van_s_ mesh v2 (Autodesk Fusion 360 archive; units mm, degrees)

design "van_s_ mesh" references "Solar Panel -  1 - Part 1"
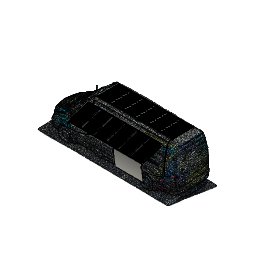
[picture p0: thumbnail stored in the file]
description: Part Number
part number: 6575N187_T-Slotted Framing Rail
base_feature "Base Feature1"
sketch "Sketch2" plane through (0, 0, 0) normal (0, 0, 1) x axis (1, 0, 0)
  line L1 (-2036.5472, 646.9234) -> (2036.5472, 646.9234)
  line L2 (-2036.5472, -646.9234) -> (-2036.5472, 646.9234)
  line L3 (2036.5472, -646.9234) -> (-2036.5472, -646.9234)
  line L4 (2036.5472, 646.9234) -> (2036.5472, -646.9234)
  line L5 (-2036.5472, -646.9234) -> (2036.5472, 646.9234)
  line L6 (2036.5472, -646.9234) -> (-2036.5472, 646.9234)
  line L7 (780, 700) -> (-780, 700)
  line L8 (780, 0) -> (780, 700)
  line L9 (-780, 0) -> (780, 0)
  line L10 (-780, 700) -> (-780, 0)
  point P6 (0, 0)
  point P1 (0, 0)
  point P7 (-780, 700)
  point P10 (-780, 0)
  point P8 (780, 700)
  horizontal L1
  perpendicular L1 L2
  parallel L1 L3
  parallel L2 L4
  coincident L5 P6
  coincident L6 P6
  coincident P1 P6
  horizontal L7
  vertical L8
  horizontal L9
  vertical L10
  midpoint P6 L9
  dimension "d1" distance P7 P10 = 700
  dimension "d2" distance P7 P8 = 1560
extrude "Extrude1" new body sketch "Sketch2" profile of L7 L8 L9 L10 along normal blind 4
copy_paste_bodies "CopyPasteBodies1"
move "Move1"
copy_paste_bodies "CopyPasteBodies2"
move "Move2"
move "Move3"
move "Move4"
move "Move5"
move "Move6"
move "Move7"
copy_paste_bodies "CopyPasteBodies3"
move "Move8"
copy_paste_bodies "CopyPasteBodies4"
move "Move9"
scale "Scale1" ScaleY 0.75
move "Move10"
sketch "Sketch3" plane through (0, 0, 0) normal (0, 0, 1) x axis (1, 0, 0)
work_plane "WorkPlane1" AlongDistance -2099.524
sketch "Sketch4" plane through (-2099.524, 0, 0) normal (1, 0, 0) x axis (0, 1, 0)
  curve K1 (-814.2732, -244.8153) -> (-965.3731, -1472.4732)
sketch "Sketch5" plane through (-2099.524, 0, 0) normal (1, 0, 0) x axis (0, 1, 0)
  line L1 (-843.7082, -238.4309) -> (-814.6312, -245.8155)
  line L2 (-997.4951, -1471.5228) -> (-967.4951, -1471.5061)
  arc A1 centre (4000.6368, -1468.7367) radius 4968.1327 clockwise from (-967.4951, -1471.5061) to (-814.6312, -245.8155)
  arc A2 centre (4000.6368, -1468.7367) radius 4998.1327 clockwise from (-997.4951, -1471.5228) to (-843.7082, -238.4309)
  dimension "d12" = 30
extrude "Extrude2" new body sketch "Sketch5" distance 40
work_plane "WorkPlane2" AlongDistance -996.132
sketch "Sketch6" plane through (0, -996.132, 0) normal (0, 1, 0) x axis (1, 0, 0)
  line L1 (-577.0426, 2211.136) -> (-2073.8842, 2211.136)
  line L2 (-577.0426, 61.2365) -> (-577.0426, 2211.136)
  line L3 (-2073.8842, 61.2365) -> (-577.0426, 61.2365)
  line L4 (-2073.8842, 2211.136) -> (-2073.8842, 61.2365)
  horizontal L1
  vertical L2
  horizontal L3
  vertical L4
work_plane "WorkPlane3" AlongDistance -2035.729
sketch "Sketch7" plane through (-2035.729, 0, 0) normal (1, 0, 0) x axis (0, 1, 0)
  arc A1 centre (3368.2029, -1386.2856) radius 4337.2066 clockwise from (-882.0776, -2250.2745) to (-772.1405, -94.4197)
extrude "Extrude3" new body blind 1452.679 second side blind 46.499
thicken "Thicken1" Thickness 12.67 bodies "mock door"
copy_paste_bodies "CopyPasteBodies5"
move "Move11"
copy_paste_bodies "CopyPasteBodies6"
move "Move12"
copy_paste_bodies "CopyPasteBodies7"
move "Move13"
sketch "Sketch8" plane through (0, 0, 0) normal (0, 0, 1) x axis (1, 0, 0)
remove_instance "RemoveInstance1"
sketch "Sketch9" plane through (0, 0, 0) normal (0, 0, 1) x axis (1, 0, 0)
  line L1 (1822.8151, -997.4951) -> (1782.8151, -997.4951)
  line L2 (1822.8151, -843.7082) -> (1822.8151, -997.4959)
  line L3 (1782.8151, -843.7082) -> (1822.8151, -843.7082)
  line L4 (1782.8151, -997.4959) -> (1782.8151, -843.7082)
  line L5 (-2079.524, -997.4951) -> (-2119.524, -997.4951)
  line L6 (-2079.524, -843.7082) -> (-2079.524, -997.4959)
  line L7 (-2119.524, -843.7082) -> (-2079.524, -843.7082)
  line L8 (-2119.524, -997.4959) -> (-2119.524, -843.7082)
  line L9 (-2079.524, -843.7082) -> (-2119.524, -843.7082)
  line L10 (-2079.524, 649.0832) -> (-2079.524, -843.7082)
  line L11 (-2119.524, 649.0832) -> (-2079.524, 649.0832)
  line L12 (-2119.524, -843.7082) -> (-2119.524, 649.0832)
  line L13 (1822.8151, -843.7082) -> (1782.8151, -843.7082)
  line L14 (1822.8151, 617.5114) -> (1822.8151, -843.7082)
  line L15 (1782.8151, 617.5114) -> (1822.8151, 617.5114)
  line L16 (1782.8151, -843.7082) -> (1782.8151, 617.5114)
  line L17 (-2155.2321, 574.112) -> (1869.3896, 574.112)
  line L18 (-2155.2321, 534.112) -> (-2155.2321, 574.112)
  line L19 (1869.3896, 534.112) -> (-2155.2321, 534.112)
  line L20 (1869.3896, 574.112) -> (1869.3896, 534.112)
  line L21 (2.5, 0) -> (20, 0)
  line L22 (1869.3896, -534.112) -> (-2155.2321, -534.112)
  line L23 (1869.3896, -574.112) -> (1869.3896, -534.112)
  line L24 (-2155.2321, -534.112) -> (-2155.2321, -574.112)
  line L25 (-2155.2321, -574.112) -> (1869.3896, -574.112)
  point P12 (-2119.524, -843.7082)
  point P14 (-2119.524, -843.7082)
  point P11 (-2079.524, -843.7082)
  point P6 (1782.8151, -843.7082)
  point P18 (1782.8151, -843.7082)
  point P5 (1822.8151, -843.7082)
  point P22 (1869.3896, 574.112)
  point P30 (1869.3896, -574.112)
  point P23 (-2155.2321, 574.112)
  point P31 (-2155.2321, -574.112)
  point P24 (-2155.2321, 534.112)
  point P28 (-2155.2321, -534.112)
  point P25 (1869.3896, 534.112)
  point P29 (1869.3896, -534.112)
  horizontal L9
  vertical L10
  horizontal L11
  vertical L12
  coincident P12 P14
  coincident P11 L10
  horizontal L13
  vertical L14
  horizontal L15
  vertical L16
  coincident P6 P18
  coincident P5 L14
  horizontal L17
  vertical L18
  horizontal L19
  vertical L20
  symmetric P22 L21 P30
  symmetric P23 L21 P31
  symmetric P24 L21 P28
  symmetric P25 L21 P29
  dimension "d22" distance P23 P24 = 40
extrude "Extrude4" new body sketch "Sketch9" profile of L17 L18 L19 L20 L22 L23 L24 L25 along normal blind 25
sketch "Sketch10" plane through (0, 0, 25) normal (0, 0, 1) x axis (-1, 0, 0)
  line L1 (-1869.3896, -574.112) -> (-1869.3896, -534.112)
  line L2 (2155.2321, -574.112) -> (-1869.3896, -574.112)
  line L3 (2155.2321, -534.112) -> (2155.2321, -574.112)
  line L4 (-1869.3896, -534.112) -> (2155.2321, -534.112)
  line L5 (2119.524, 843.7082) -> (2119.524, -649.0832)
  line L6 (-1822.8151, -617.5114) -> (-1822.8151, 843.7082)
  line L7 (-1822.8151, -574.112) -> (2119.524, -574.112)
  line L8 (-1822.8151, 575.888) -> (-1822.8151, -574.112)
  line L9 (2119.524, 575.888) -> (-1822.8151, 575.888)
  line L10 (2119.524, -574.112) -> (2119.524, 575.888)
  line L11 (2119.524, 0.888) -> (0, 0)
  line L12 (2079.524, -534.112) -> (2079.524, 535.888)
  line L13 (-1782.8151, -534.112) -> (2079.524, -534.112)
  line L14 (-1782.8151, 535.888) -> (-1782.8151, -534.112)
  line L15 (2079.524, 535.888) -> (-1782.8151, 535.888)
  point P12 (-1822.8151, 575.888)
  point P10 (2119.524, -574.112)
  point P1 (0, 0)
  point P14 (0, 0)
  point P15 (2119.524, 0.888)
  point P11 (-1822.8151, -574.112)
  horizontal L7
  vertical L8
  horizontal L9
  vertical L10
  coincident L6 P12
  coincident L5 P10
  coincident L2 P10
  coincident P1 P14
  midpoint L10 P15
  dimension "d25" distance P11 P12 = 1150
  dimension "d26" = 40
extrude "Extrude5" new body sketch "Sketch10" profile of L2 L4 L5 L6 L7 L8 L9 L10 L15 L14 L13 L12 along normal blind 40
work_plane "WorkPlane4"
sketch "Sketch11" plane through (0, 574.112, 0) normal (0, 1, 0) x axis (-1, 0, 0)
  line L1 (2119.524, 25) -> (-1822.8151, 25)
  line L2 (2119.524, 65) -> (2119.524, 25)
  line L3 (-1822.8151, 65) -> (2119.524, 65)
  line L4 (-1822.8151, 25) -> (-1822.8151, 65)
copy_paste_bodies "CopyPasteBodies8"
move "Move14"
sketch "Sketch12" plane through (-2119.524, 0, 0) normal (-1, 0, 0) x axis (0, -1, 0)
  line L1 (575.888, 75) -> (-574.112, 75)
  line L2 (575.888, 115) -> (575.888, 75)
  line L3 (-574.112, 115) -> (575.888, 115)
  line L4 (-574.112, 75) -> (-574.112, 115)
  line L5 (814.6312, -245.8155) -> (843.7082, -238.4309)
  line L6 (997.4951, -1471.5228) -> (967.4951, -1471.5061)
  line L7 (575.888, 65) -> (575.888, 25)
  curve K1 (843.7082, -238.4309) -> (575.888, 65)
  curve K2 (853.8697, -278.4421) -> (833.5466, -198.4197)
  curve K3 (636.8867, 65) -> (514.8894, 65)
  curve K4 (814.6312, -245.8155) -> (575.888, 25)
  curve K5 (621.2142, 25) -> (530.5619, 25)
  curve K6 (827.5497, -296.682) -> (801.7128, -194.949)
  arc A1 centre (-4000.6368, -1468.7367) radius 4968.1327 clockwise from (814.6312, -245.8155) to (967.4951, -1471.5061)
  arc A2 centre (-4000.6368, -1468.7367) radius 4998.1327 clockwise from (843.7082, -238.4309) to (997.4951, -1471.5228)
  point P12 (575.888, 65)
  point P13 (575.888, 65)
  point P6 (843.7082, -238.4309)
  point P14 (843.7082, -238.4309)
  point P11 (575.888, 25)
  point P19 (575.888, 25)
  point P7 (814.6312, -245.8155)
  point P20 (814.6312, -245.8155)
  coincident P12 P13
  coincident P6 P14
  midpoint P14 K2
  tangent A2 K2
  midpoint P13 K3
  perpendicular L7 K3
  coincident P11 P19
  coincident P7 P20
  midpoint P19 K5
  perpendicular L7 K5
  midpoint P20 K6
  perpendicular L5 K6
extrude "Extrude6" new body sketch "Sketch12" profile of L5 L7 K1 K4 against normal blind 40
copy_paste_bodies "CopyPasteBodies9"
move "Move15"
step "SurfaceOffset" offset 0
thicken "Thicken2" Thickness 20
copy_paste_bodies "CopyPasteBodies10"
move "Move16"
copy_paste_bodies "CopyPasteBodies11"
move "Move17"
move "Move18"
move "Move19"
sketch "Sketch13" plane through (0, 0, 65) normal (0, 0, 1) x axis (-1, 0, 0)
  line L1 (-1782.8151, 535.888) -> (-1782.8151, -534.112)
  line L2 (2079.524, 535.888) -> (-1782.8151, 535.888)
  line L3 (2079.524, -534.112) -> (2079.524, 535.888)
  line L4 (-1782.8151, -534.112) -> (2079.524, -534.112)
  line L5 (-1822.8151, 575.888) -> (2119.524, 575.888)
  line L6 (-1822.8151, -574.112) -> (-1822.8151, 575.888)
  line L7 (2119.524, -574.112) -> (-1822.8151, -574.112)
  line L8 (2119.524, 575.888) -> (2119.524, -574.112)
  line L9 (1467.0268, -534.112) -> (2049.0268, -534.112)
  line L10 (1467.0268, 558.888) -> (1467.0268, -534.112)
  line L11 (2049.0268, 558.888) -> (1467.0268, 558.888)
  line L12 (2049.0268, -534.112) -> (2049.0268, 558.888)
  point P10 (2049.0268, -534.112)
  point P11 (1467.0268, -534.112)
  point P12 (1467.0268, 558.888)
  horizontal L9
  vertical L10
  horizontal L11
  vertical L12
  coincident L4 P10
  dimension "d33" distance P11 P12 = 1093
  dimension "d34" distance P10 P11 = 582
component_insert "Component Insert1"
rectangular_pattern "00000000-0000-0000-0000-000000000000" uSpaceDistance 3247.017 vSpaceDistance 0
component_from_bodies "Body->Comp1"
copy_paste "CutPaste1"
copy_paste "CutPaste2"
copy_paste "CutPaste3"
copy_paste "CutPaste4"
copy_paste "CutPaste5"
copy_paste "CutPaste6"
base_feature "Base Feature1"
component_insert "Component Insert1"
copy_paste "CutPaste2"
copy_paste "CutPaste3"
copy_paste "CutPaste4"
copy_paste "CutPaste5"
copy_paste "CutPaste6"
position "Position1"
component_from_bodies "Body->Comp2"
component_from_bodies "Body->Comp3"
component_from_bodies "Body->Comp4"
component_from_bodies "Body->Comp5"
copy_paste_bodies "CutPasteBodies1"
copy_paste_bodies "CutPasteBodies1"
position "Position2"
sketch "Sketch14" plane through (1822.8151, 0, 0) normal (1, 0, 0) x axis (0, 1, 0)
  line L1 (574.112, 25) -> (-575.888, 25)
  line L2 (574.112, 65) -> (574.112, 25)
  line L3 (-575.888, 65) -> (574.112, 65)
  line L4 (-575.888, 25) -> (-575.888, 65)
  line L5 (-575.888, 45) -> (574.112, 45)
  line L6 (-575.888, 85) -> (-575.888, 45)
  line L7 (574.112, 85) -> (-575.888, 85)
  line L8 (574.112, 45) -> (574.112, 85)
  point P6 (574.112, 45)
  point P7 (-575.888, 45)
  point P8 (-575.888, 85)
  horizontal L5
  vertical L6
  horizontal L7
  vertical L8
  midpoint L2 P6
  dimension "d39" distance P7 P8 = 40
split "Split1"
split "Split2"
sketch "Sketch1" plane through (0, 574.112, 0) normal (0, 1, 0) x axis (-1, 0, 0)
  line L1 (-1787.8151, 50) -> (-1817.8151, 50)
  line L2 (-1787.8151, 80) -> (-1787.8151, 50)
  line L3 (-1817.8151, 80) -> (-1787.8151, 80)
  line L4 (-1817.8151, 50) -> (-1817.8151, 80)
  line L5 (-1782.8151, 25) -> (-1822.8151, 25)
  line L6 (-1822.8151, 65) -> (-1822.8151, 25)
  line L7 (-1782.8151, 65) -> (-1782.8151, 25)
  line L8 (-1822.8151, 65) -> (-1782.8151, 65)
  line L9 (-1802.8151, 80) -> (-1802.8151, 65)
  line L10 (-1817.8151, 50) -> (-1787.8151, 80)
  line L11 (-1829.8151, 76) -> (-1805.8151, 76)
  line L12 (-1829.8151, 54) -> (-1829.8151, 76)
  line L13 (-1805.8151, 54) -> (-1829.8151, 54)
  line L14 (-1805.8151, 76) -> (-1805.8151, 54)
  line L15 (-1829.8151, 54) -> (-1805.8151, 76)
  line L16 (-1805.8151, 54) -> (-1829.8151, 76)
  line L17 (-1799.8151, 54) -> (-1775.8151, 54)
  line L18 (-1799.8151, 76) -> (-1799.8151, 54)
  line L19 (-1775.8151, 54) -> (-1775.8151, 76)
  line L20 (-1775.8151, 76) -> (-1799.8151, 76)
  point P10 (-1802.8151, 65)
  point P11 (-1802.8151, 80)
  point P16 (-1817.8151, 65)
  point P12 (-1805.8151, 76)
  point P19 (-1799.8151, 76)
  point P13 (-1829.8151, 76)
  point P20 (-1775.8151, 76)
  point P14 (-1829.8151, 54)
  point P17 (-1775.8151, 54)
  point P15 (-1805.8151, 54)
  point P18 (-1799.8151, 54)
  point P3 (-1787.8151, 50)
  point P4 (-1787.8151, 80)
  point P5 (-1817.8151, 80)
  horizontal L1
  vertical L2
  horizontal L3
  vertical L4
  midpoint L8 P10
  midpoint L3 P11
  vertical L9
  midpoint P10 L10
  horizontal L11
  perpendicular L11 L12
  parallel L11 L13
  parallel L12 L14
  coincident L15 P16
  coincident L16 P16
  midpoint L4 P16
  symmetric L9 P12 P19
  symmetric L9 P13 P20
  symmetric L9 P14 P17
  symmetric L9 P15 P18
  dimension "d40" distance P3 P4 = 30
  dimension "d41" distance P4 P5 = 30
  dimension "d42" distance L3 L11 = 4
  dimension "d43" distance L9 L14 = 3
extrude "Extrude1" new body sketch "Sketch1" profile of L1 L2 L3 L4 L8 L11 L13 L14 L17 L18 L20 to an object
copy_paste_bodies "CutPasteBodies12"
component_from_bodies "Body->Comp6"
mirror_component "MirrorComponent1"
derived_instance "DerivedInstance1"
combine "Combine1"
combine "Combine2"
joint "Assemble1" alignAngle 0 alignOffsetX 0 alignOffsetY 0 alignOffsetZ 0
joint "Assemble2" alignAngle 0 alignOffsetX 0 alignOffsetY 0 alignOffsetZ 0
joint "Assemble3" alignAngle 0 alignOffsetX 0 alignOffsetY 0 alignOffsetZ 0
joint "Assemble4" alignAngle 180 alignOffsetX 0 alignOffsetY 0 alignOffsetZ 0
component_from_bodies "Body->Comp1"
position "Position3"
joint "Assemble5" alignAngle 90 alignOffsetX 0 alignOffsetY 0 alignOffsetZ 0
as_built_joint "As-built1"
joint "Assemble6" alignAngle 0 alignOffsetX 0 alignOffsetY 0 alignOffsetZ 0
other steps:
base_feature "Base Feature1"
base_feature "Base Feature1"
base_feature "Base Feature1"
base_feature "Base Feature1"
derived_base_feature "Derived Base Feature"
base_feature "Base Feature1"
base_feature "Base Feature1"
base_feature "Base Feature2"
base_feature "Base Feature2"
base_feature "Base Feature1"
base_feature "Base Feature2"
base_feature "Base Feature3"
base_feature "Base Feature4"
base_feature "Base Feature5"
base_feature "Base Feature6" bodies "mock door", "mock door (1)"
base_feature "Base Feature7"
base_feature "Base Feature8"
base_feature "Base Feature9"
base_feature "Base Feature10"
base_feature "Base Feature11"
base_feature "Base Feature12"
base_feature "Base Feature13"
create_component "CreateComponent4"
create_component "CreateComponent5"
create_component "CreateComponent6"
remove_body "RemoveBody1"
remove_instance "RemoveInstance2"
remove_instance "RemoveInstance3"
remove_instance "RemoveInstance4"
remove_instance "RemoveInstance5"
remove_instance "RemoveInstance6"
remove_instance "RemoveInstance7"
create_component "CreateComponent7"
create_component "CreateComponent8"
remove_body "RemoveBody2"
create_component "CreateComponent9"
remove_body "RemoveBody3"
create_component "CreateComponent10"
remove_body "RemoveBody4"
create_component "CreateComponent11"
remove_body "RemoveBody5"
remove_body "RemoveBody6"
remove_body "RemoveBody7"
remove_body "RemoveBody1"
create_component "CreateComponent12"
remove_body "RemoveBody8"
create_component "CreateComponent13"
joint_origin "JointOrigin1"
joint_origin "JointOrigin1"
joint_origin "JointOrigin2"
joint_origin "JointOrigin1"
joint_origin "JointOrigin2"
joint_origin "JointOrigin1"
joint_origin "JointOrigin2"
joint_origin "JointOrigin1"
create_component "CreateComponent1"
remove_body "RemoveBody1"
joint_origin "JointOrigin1"
joint_origin "JointOrigin1"
joint_origin "JointOrigin2"
joint_origin "JointOrigin1"
named bodies: "mock door", "mock door (1)"

design "Solar Panel -  1 - Part 1"
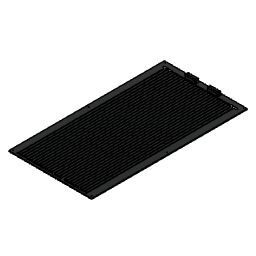
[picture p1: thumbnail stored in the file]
description: STEP AP242
part number: Part 1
